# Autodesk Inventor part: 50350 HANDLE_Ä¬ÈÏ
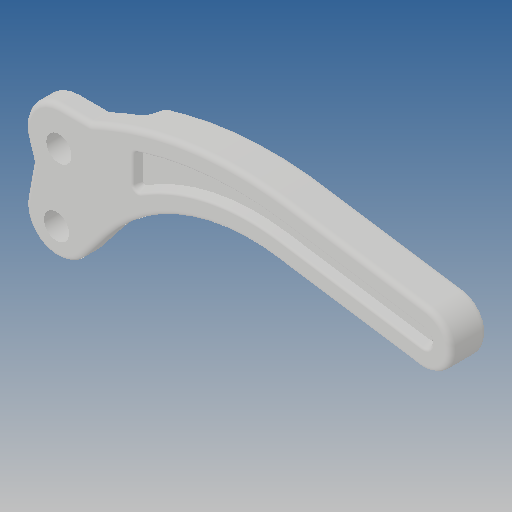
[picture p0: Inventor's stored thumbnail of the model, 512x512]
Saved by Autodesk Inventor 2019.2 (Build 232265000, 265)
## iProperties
Created: 2010-06
Part Number: 50350 HANDLE_Ä¬ÈÏ
Material: Ogólny
Document SubType Name: Modeling
Designer: CADENGINEERING4
Density: 1 g/cm^3
Appearance: Domyślna
Author: CADENGINEERING4
Revision Number: ÈÎºÎ
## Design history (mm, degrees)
feature "NONE"
node "Bryła1"
